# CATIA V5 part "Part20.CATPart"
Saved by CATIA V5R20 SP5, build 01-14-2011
Part number: Part1
Material "Water": density 1000 kg/m3
Bounding box of the stored display mesh (mm): x -60 to 60, y -60 to 60, z -65 to 65
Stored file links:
  D:\新建文件夹\Part20.CATPart
  C:\Program Files\Dassault Systemes\B20\intel_a\startup\materials\Catalog.CATMaterial
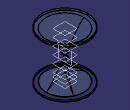
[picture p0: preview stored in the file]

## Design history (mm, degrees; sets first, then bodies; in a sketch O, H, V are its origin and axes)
Body1 (main body)
  Plane1: type Offset, RefPlane xy-plane, Offset 20, reversed
  Set1
    Plane2: type Offset, RefPlane xy-plane, Offset 40 {= Plane1.Offset * 2}, reversed
    Plane3: type Offset, RefPlane xy-plane, Offset 60 {= Plane1.Offset * 3}, reversed
  Plane4: type Offset, RefPlane xy-plane, Offset 20
  Set2
    Plane5: type Offset, RefPlane xy-plane, Offset 40 {= Plane4.Offset * 2}
    Plane6: type Offset, RefPlane xy-plane, Offset 60 {= Plane4.Offset * 3}
  Sketch1 on Plane6, origin (0, 0, 60), H (1, 0, 0), V (0, 1, 0)
    circle A1 centre (0, 0) radius 60
    point P1 (60, 0)
    coincidence: A1 P1, P1 H
  Sketch2 on Plane3, origin (0, 0, -60), H (1, 0, 0), V (0, 1, 0)
    circle A1 centre (0, 0) radius 60
  Pad1: profile Sketch2, direction (0, 0, -1), length 5
  Pad2: profile Sketch1, direction (0, 0, 1), length 5
  Sketch3 on xy-plane, origin (0, 0, 0), H (1, 0, 0), V (0, 1, 0)
    circle A1 centre (0, 0) radius 4
    radius A1 = 4
  Sketch4 on Plane1, origin (0, 0, -20), H (1, 0, 0), V (0, 1, 0)
    circle A1 centre (0, 0) radius 16
    radius A1 = 16
  Sketch5 on Plane2, origin (0, 0, -40), H (1, 0, 0), V (0, 1, 0)
    circle A1 centre (0, 0) radius 30
    point P1 (30, 0)
    coincidence: A1 P1, P1 H
  Sketch6 on Plane3, origin (0, 0, -60), H (1, 0, 0), V (0, 1, 0)
    circle A1 centre (0, 0) radius 50
    point P1 (50, 0)
    coincidence: A1 P1, P1 H
  Loft1: solid, Sections (Sketch3; Sketch4; Sketch5; Sketch6)
  Sketch7 on xy-plane, origin (0, 0, 0), H (1, 0, 0), V (0, 1, 0)
    circle A1 centre (0, 0) radius 4
    radius A1 = 4
  Sketch8 on Plane4, origin (0, 0, 20), H (1, 0, 0), V (0, 1, 0)
    circle A1 centre (0, 0) radius 16
    radius A1 = 16
  Sketch9 on Plane5, origin (0, 0, 40), H (1, 0, 0), V (0, 1, 0)
    circle A1 centre (0, 0) radius 30
    radius A1 = 30
  Sketch10 on Plane6, origin (0, 0, 60), H (1, 0, 0), V (0, 1, 0)
    circle A1 centre (0, 0) radius 50
    radius A1 = 50
  Loft2: solid, Sections (Sketch7; Sketch8; Sketch9; Sketch10)
  Shell1: ExtOffset 0, Face end face of Pad2, IntOffset 1
Body2, material "Water"
  Sketch11 on yz-plane, origin (0, 0, 0), H (0, 1, 0), V (0, 0, 1)
    line L1 (0, 0) -> (0, 20)
    line L2 (0, 20) -> (15, 20)
    line L3 (0, 0) -> (3, 0)
    line L4 (3, 0) -> (15, 20)
    length L2 = 15
    length L3 = 3
    vertical: L1 V
    horizontal: L2 H, L3 H
  Shaft1: profile Sketch11, axis Sketch11.V, angle 360
  Sketch12 on Plane3, origin (0, 0, -60), H (1, 0, 0), V (0, 1, 0)
    circle A1 centre (0, 0) radius 49
    radius A1 = 49
  Plane7: type Offset, RefPlane Plane2, Offset 10, reversed
  Sketch13 on Plane7, origin (0, 0, -50), H (1, 0, 0), V (0, 1, 0)
    circle A1 centre (0, 0) radius 29
    radius A1 = 29
  Sketch14 on Plane2, origin (0, 0, -40), H (1, 0, 0), V (0, 1, 0)
    circle A1 centre (0, 0) radius 1
    radius A1 = 1
  Loft3: solid, Sections (Sketch12; Sketch13; Sketch14)
  Sketch15 on Plane6, origin (0, 0, 60), H (1, 0, 0), V (0, 1, 0)
    circle A1 centre (0, 0) radius 59
    radius A1 = 59
  Pad3: profile Sketch15, direction (0, 0, 1), length 5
